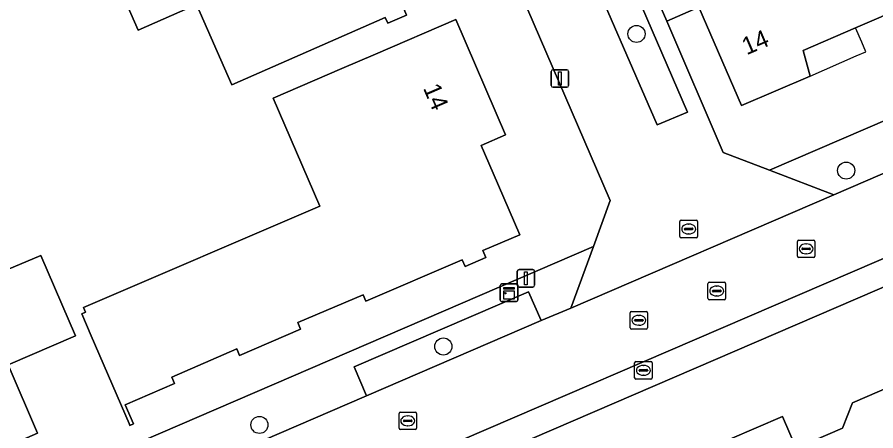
# Model space of a CAD drawing. Extents: x 157767 to 159172, y 387839 to 389425.
# Drawn here: x 158122.64 to 158171.64, y 388718.27 to 388741.89 of the extents above; entities that cross this region are included whole.
import ezdxf

# ---------------------------------------------------------------- set-up
doc = ezdxf.new("R2010")
doc.units = 0
for name, color, linetype in [('IMGEO_Boom', 7, 'Continuous'), ('IMGEO_Brandkraan', 7, 'Continuous'), ('IMGEO_Erf', 7, 'Continuous'), ('IMGEO_Kast', 7, 'Continuous'), ('IMGEO_Kolk', 7, 'Continuous'), ('IMGEO_Lichtmast', 7, 'Continuous'), ('IMGEO_Pand', 7, 'Continuous'), ('IMGEO_Pand_nummerreeks', 7, 'Continuous'), ('IMGEO_Pand_overbouw', 7, 'Continuous'), ('IMGEO_Parkeervlak_open', 7, 'Continuous'), ('IMGEO_Rijbaan_lokaal_open', 7, 'Continuous'), ('IMGEO_Rioolput', 7, 'Continuous'), ('IMGEO_Voetpad_open', 7, 'Continuous')]:
    doc.layers.add(name, color=color, linetype=linetype)

msp = doc.modelspace()

# ---------------------------------------------------------------- linework, layer by layer
at = {"layer": 'IMGEO_Boom'}
for centre in [(158157.983, 388740.927), (158169.948, 388733.125), (158146.961, 388723.083), (158136.464, 388718.604)]:
    msp.add_circle(centre, 0.489, dxfattribs=at)
at = {"layer": 'IMGEO_Brandkraan'}
for p, q in [((158157.876, 388721.292), (158157.876, 388722.144)), ((158157.951, 388722.218), (158158.803, 388722.218)), ((158158.364, 388721.998), (158158.389, 388721.998)), ((158158.877, 388722.144), (158158.877, 388721.292)), ((158158.135, 388721.712), (158158.135, 388721.724)), ((158158.573, 388721.675), (158158.175, 388721.675)), ((158158.178, 388721.761), (158158.576, 388721.761)), ((158158.387, 388721.438), (158158.362, 388721.438)), ((158158.619, 388721.724), (158158.619, 388721.712)), ((158158.803, 388721.218), (158157.951, 388721.218))]:
    msp.add_line(p, q, dxfattribs=at)
for points in [[(158157.876, 388721.292), (158157.876, 388722.144)], [(158157.951, 388722.218), (158158.803, 388722.218)], [(158158.877, 388722.144), (158158.877, 388721.292)], [(158158.803, 388721.218), (158157.951, 388721.218)]]:
    msp.add_lwpolyline(points, dxfattribs=at)
for centre, radius, start, end in [((158157.953, 388722.142), 0.0765, 91.552, 178.448), ((158157.953, 388722.142), 0.0765, 91.552, 178.448), ((158158.801, 388722.142), 0.0765, 1.552, 88.448), ((158158.801, 388722.142), 0.0765, 1.552, 88.448), ((158158.175, 388721.721), 0.0403, 85.8775, 175.7526), ((158158.172, 388721.711), 0.0366, 178.938, 274.7102), ((158158.576, 388721.718), 0.043, 264.8664, 352.4533), ((158158.58, 388721.723), 0.0386, 1.7309, 96.639), ((158157.953, 388721.294), 0.0765, 181.552, 268.448), ((158157.953, 388721.294), 0.0765, 181.552, 268.448), ((158158.801, 388721.294), 0.0765, 271.552, 358.448), ((158158.801, 388721.294), 0.0765, 271.552, 358.448)]:
    msp.add_arc(centre, radius, start, end, dxfattribs=at)
for centre, major_axis, ratio, start_param, end_param in [((158158.363, 388721.718), (-0.387, 0.002), 0.722429, 4.712389, 7.853982), ((158158.388, 388721.718), (-0.39, 0.002), 0.717154, 1.570796, 4.712389)]:
    msp.add_ellipse(centre, major_axis=major_axis, ratio=ratio, start_param=start_param, end_param=end_param, dxfattribs=at)
at = {"layer": 'IMGEO_Erf'}
for points in [[(158128.121, 388749.432), (158129.068, 388749.847), (158130.979, 388750.683), (158131.778, 388751.032), (158136.358, 388753.036), (158137.65, 388750.084), (158142.754, 388752.318), (158143.769, 388750), (158143.853, 388749.808), (158144.292, 388750), (158144.584, 388750.128), (158144.639, 388750), (158147.435, 388743.516), (158144.716, 388742.327), (158144.859, 388742.003), (158143.786, 388741.533), (158143.644, 388741.858), (158134.884, 388738.025), (158132.881, 388742.604), (158129.54, 388741.142), (158127.585, 388745.614), (158129.437, 388746.424)], [(158139.903, 388731.092), (158137.252, 388737.268), (158141.162, 388738.946), (158143.084, 388739.771), (158147.678, 388741.743), (158150.503, 388735.164), (158149.116, 388734.564), (158149.799, 388732.985), (158151.322, 388729.462), (158149.213, 388728.553), (158149.385, 388728.153), (158148.2, 388727.641), (158148.03, 388728.036), (158142.533, 388725.665), (158142.376, 388726.033), (158138.652, 388724.443), (158138.806, 388724.073), (158135.331, 388722.574), (158135.173, 388722.942), (158131.456, 388721.335), (158131.616, 388720.967), (158128.798, 388719.751), (158129.27, 388718.659), (158129.07, 388718.573), (158129.026, 388718.675), (158126.863, 388723.689), (158126.321, 388724.946), (158126.541, 388725.04), (158126.426, 388725.306)], [(158182.445, 388701.959), (158177.657, 388699.85), (158173.023, 388710.594), (158169.625, 388709.129), (158170.139, 388707.935), (158166.465, 388706.351), (158163.787, 388712.559), (158161.807, 388717.15), (158166.312, 388719.092), (158167.091, 388717.285), (158169.735, 388718.425), (158170.309, 388719.869), (158174.095, 388721.502), (158176.075, 388716.911)]]:
    msp.add_lwpolyline(points, close=True, dxfattribs=at)
for points in [[(158117.739, 388745.138), (158119.269, 388741.573), (158111.6, 388738.281), (158115.856, 388728.369), (158114.939, 388727.976), (158116.218, 388724.995), (158123.988, 388728.285), (158125.961, 388723.69), (158122.118, 388722.028), (158123.799, 388718.137), (158121.38, 388717.092), (158116.266, 388714.882), (158111.105, 388712.651), (158108.695, 388711.61), (158109.311, 388710.185), (158104.688, 388708.207), (158104.74, 388708.086), (158104.538, 388707.998), (158104.988, 388707.005), (158155.532, 388728.793), (158156.474, 388731.409), (158148.476, 388750)], [(158173.448, 388742.548), (158170.488, 388741.27), (158167.498, 388739.979), (158167.894, 388738.519), (158163.973, 388736.84), (158161.536, 388742.453), (158159.71, 388741.661), (158162.924, 388734.167), (158165.563, 388733.146), (158187.619, 388742.643)], [(158199.515, 388738.309), (158146.245, 388715.336), (158145.347, 388712.435), (158152.598, 388695.598), (158155.311, 388689.297), (158156.854, 388685.715), (158162.739, 388672.05), (158167.203, 388661.684), (158171.568, 388659.372), (158223.84, 388681.871)]]:
    msp.add_lwpolyline(points, dxfattribs=at)
at = {"layer": 'IMGEO_Kast'}
for p, q in [((158150.21, 388725.728), (158150.21, 388726.569)), ((158150.21, 388726.569), (158150.21, 388725.728)), ((158150.285, 388726.653), (158151.126, 388726.653)), ((158151.126, 388726.653), (158150.285, 388726.653)), ((158151.21, 388726.578), (158151.21, 388725.737)), ((158151.21, 388725.737), (158151.21, 388726.578)), ((158151.135, 388725.653), (158150.294, 388725.653)), ((158150.294, 388725.653), (158151.135, 388725.653))]:
    msp.add_line(p, q, dxfattribs=at)
for points in [[(158150.405, 388726.443), (158151.005, 388726.443), (158151.005, 388726.358), (158150.405, 388726.358), (158150.405, 388726.443)], [(158150.405, 388726.268), (158151.005, 388726.268), (158151.005, 388725.779), (158150.405, 388725.779), (158150.405, 388726.268)]]:
    msp.add_lwpolyline(points, dxfattribs=at)
msp.add_circle((158150.489, 388726.117), 0.0377, dxfattribs=at)
for centre, start, end in [((158150.288, 388726.575), 92.4484, 184.2845), ((158150.288, 388726.575), 92.4484, 184.2845), ((158151.132, 388726.575), 2.4484, 94.2845), ((158151.132, 388726.575), 2.4484, 94.2845), ((158150.288, 388725.731), 182.4484, 274.2845), ((158150.288, 388725.731), 182.4484, 274.2845), ((158151.132, 388725.731), 272.4484, 4.2845), ((158151.132, 388725.731), 272.4484, 4.2845)]:
    msp.add_arc(centre, 0.0779, start, end, dxfattribs=at)
at = {"layer": 'IMGEO_Kolk'}
for p, q in [((158160.459, 388729.362), (158160.459, 388730.214)), ((158160.534, 388730.288), (158161.386, 388730.288)), ((158161.46, 388730.214), (158161.46, 388729.362)), ((158160.718, 388729.782), (158160.718, 388729.794)), ((158161.156, 388729.745), (158160.758, 388729.745)), ((158160.761, 388729.831), (158161.159, 388729.831)), ((158160.947, 388730.068), (158160.972, 388730.068)), ((158161.202, 388729.794), (158161.202, 388729.782)), ((158161.386, 388729.288), (158160.534, 388729.288)), ((158160.97, 388729.508), (158160.945, 388729.508)), ((158167.162, 388728.232), (158167.162, 388729.084)), ((158167.237, 388729.158), (158168.089, 388729.158)), ((158167.464, 388728.701), (158167.862, 388728.701)), ((158167.65, 388728.938), (158167.675, 388728.938)), ((158168.163, 388729.084), (158168.163, 388728.232)), ((158167.421, 388728.652), (158167.421, 388728.664)), ((158167.859, 388728.615), (158167.461, 388728.615)), ((158167.673, 388728.378), (158167.648, 388728.378)), ((158167.905, 388728.664), (158167.905, 388728.652)), ((158168.089, 388728.158), (158167.237, 388728.158)), ((158157.615, 388724.152), (158157.615, 388725.004)), ((158157.69, 388725.078), (158158.542, 388725.078)), ((158158.103, 388724.858), (158158.128, 388724.858)), ((158158.616, 388725.004), (158158.616, 388724.152)), ((158157.874, 388724.572), (158157.874, 388724.584)), ((158158.312, 388724.535), (158157.914, 388724.535)), ((158157.917, 388724.621), (158158.315, 388724.621)), ((158158.126, 388724.298), (158158.101, 388724.298)), ((158158.358, 388724.584), (158158.358, 388724.572)), ((158158.542, 388724.078), (158157.69, 388724.078)), ((158144.429, 388718.411), (158144.429, 388719.263)), ((158144.504, 388719.337), (158145.356, 388719.337)), ((158144.917, 388719.117), (158144.942, 388719.117)), ((158145.43, 388719.263), (158145.43, 388718.411)), ((158144.688, 388718.831), (158144.688, 388718.843)), ((158145.126, 388718.794), (158144.728, 388718.794)), ((158144.731, 388718.88), (158145.129, 388718.88)), ((158144.94, 388718.557), (158144.915, 388718.557)), ((158145.172, 388718.843), (158145.172, 388718.831)), ((158145.356, 388718.337), (158144.504, 388718.337))]:
    msp.add_line(p, q, dxfattribs=at)
for points in [[(158160.459, 388729.362), (158160.459, 388730.214)], [(158160.534, 388730.288), (158161.386, 388730.288)], [(158161.46, 388730.214), (158161.46, 388729.362)], [(158161.386, 388729.288), (158160.534, 388729.288)], [(158167.162, 388728.232), (158167.162, 388729.084)], [(158167.237, 388729.158), (158168.089, 388729.158)], [(158168.163, 388729.084), (158168.163, 388728.232)], [(158168.089, 388728.158), (158167.237, 388728.158)], [(158157.615, 388724.152), (158157.615, 388725.004)], [(158157.69, 388725.078), (158158.542, 388725.078)], [(158158.616, 388725.004), (158158.616, 388724.152)], [(158158.542, 388724.078), (158157.69, 388724.078)], [(158144.429, 388718.411), (158144.429, 388719.263)], [(158144.504, 388719.337), (158145.356, 388719.337)], [(158145.43, 388719.263), (158145.43, 388718.411)], [(158145.356, 388718.337), (158144.504, 388718.337)]]:
    msp.add_lwpolyline(points, dxfattribs=at)
for centre, radius, start, end in [((158160.536, 388730.212), 0.0765, 91.552, 178.448), ((158160.536, 388730.212), 0.0765, 91.552, 178.448), ((158161.384, 388730.212), 0.0765, 1.552, 88.448), ((158161.384, 388730.212), 0.0765, 1.552, 88.448), ((158160.758, 388729.791), 0.0403, 85.8775, 175.7526), ((158160.755, 388729.781), 0.0366, 178.938, 274.7102), ((158161.159, 388729.788), 0.043, 264.8664, 352.4533), ((158161.163, 388729.793), 0.0386, 1.7309, 96.639), ((158160.536, 388729.364), 0.0765, 181.552, 268.448), ((158160.536, 388729.364), 0.0765, 181.552, 268.448), ((158161.384, 388729.364), 0.0765, 271.552, 358.448), ((158161.384, 388729.364), 0.0765, 271.552, 358.448), ((158167.239, 388729.082), 0.0765, 91.552, 178.448), ((158167.239, 388729.082), 0.0765, 91.552, 178.448), ((158167.461, 388728.661), 0.0403, 85.8775, 175.7526), ((158167.866, 388728.663), 0.0386, 1.7309, 96.639), ((158168.087, 388729.082), 0.0765, 1.552, 88.448), ((158168.087, 388729.082), 0.0765, 1.552, 88.448), ((158167.239, 388728.234), 0.0765, 181.552, 268.448), ((158167.239, 388728.234), 0.0765, 181.552, 268.448), ((158167.458, 388728.651), 0.0366, 178.938, 274.7102), ((158167.862, 388728.658), 0.043, 264.8664, 352.4533), ((158168.087, 388728.234), 0.0765, 271.552, 358.448), ((158168.087, 388728.234), 0.0765, 271.552, 358.448), ((158157.692, 388725.002), 0.0765, 91.552, 178.448), ((158157.692, 388725.002), 0.0765, 91.552, 178.448), ((158158.54, 388725.002), 0.0765, 1.552, 88.448), ((158158.54, 388725.002), 0.0765, 1.552, 88.448), ((158157.914, 388724.581), 0.0403, 85.8775, 175.7526), ((158157.911, 388724.571), 0.0366, 178.938, 274.7102), ((158158.315, 388724.578), 0.043, 264.8664, 352.4533), ((158158.319, 388724.583), 0.0386, 1.7309, 96.639), ((158157.692, 388724.154), 0.0765, 181.552, 268.448), ((158157.692, 388724.154), 0.0765, 181.552, 268.448), ((158158.54, 388724.154), 0.0765, 271.552, 358.448), ((158158.54, 388724.154), 0.0765, 271.552, 358.448), ((158144.506, 388719.261), 0.0765, 91.552, 178.448), ((158144.506, 388719.261), 0.0765, 91.552, 178.448), ((158145.354, 388719.261), 0.0765, 1.552, 88.448), ((158145.354, 388719.261), 0.0765, 1.552, 88.448), ((158144.506, 388718.413), 0.0765, 181.552, 268.448), ((158144.506, 388718.413), 0.0765, 181.552, 268.448), ((158144.728, 388718.84), 0.0403, 85.8775, 175.7526), ((158144.725, 388718.83), 0.0366, 178.938, 274.7102), ((158145.129, 388718.837), 0.043, 264.8664, 352.4533), ((158145.133, 388718.842), 0.0386, 1.7309, 96.639), ((158145.354, 388718.413), 0.0765, 271.552, 358.448), ((158145.354, 388718.413), 0.0765, 271.552, 358.448)]:
    msp.add_arc(centre, radius, start, end, dxfattribs=at)
for centre, major_axis, ratio, start_param, end_param in [((158160.946, 388729.788), (-0.387, 0.002), 0.722429, 4.712389, 7.853982), ((158160.971, 388729.788), (-0.39, 0.002), 0.717154, 1.570796, 4.712389), ((158167.649, 388728.658), (-0.387, 0.002), 0.722429, 4.712389, 7.853982), ((158167.674, 388728.658), (-0.39, 0.002), 0.717154, 1.570796, 4.712389), ((158158.102, 388724.578), (-0.387, 0.002), 0.722429, 4.712389, 7.853982), ((158158.127, 388724.578), (-0.39, 0.002), 0.717154, 1.570796, 4.712389), ((158144.916, 388718.837), (-0.387, 0.002), 0.722429, 4.712389, 7.853982), ((158144.941, 388718.837), (-0.39, 0.002), 0.717154, 1.570796, 4.712389)]:
    msp.add_ellipse(centre, major_axis=major_axis, ratio=ratio, start_param=start_param, end_param=end_param, dxfattribs=at)
at = {"layer": 'IMGEO_Lichtmast'}
for p, q in [((158153.118, 388737.984), (158153.118, 388738.784)), ((158153.118, 388738.784), (158153.118, 388737.984)), ((158153.218, 388738.884), (158154.008, 388738.884)), ((158154.008, 388738.884), (158153.218, 388738.884)), ((158154.108, 388738.784), (158154.108, 388737.984)), ((158154.108, 388737.984), (158154.108, 388738.784)), ((158154.008, 388737.884), (158153.218, 388737.884)), ((158153.218, 388737.884), (158154.008, 388737.884)), ((158151.177, 388726.574), (158151.177, 388727.374)), ((158151.177, 388727.374), (158151.177, 388726.574)), ((158151.277, 388727.474), (158152.067, 388727.474)), ((158152.067, 388727.474), (158151.277, 388727.474)), ((158152.167, 388727.374), (158152.167, 388726.574)), ((158152.167, 388726.574), (158152.167, 388727.374)), ((158152.067, 388726.474), (158151.277, 388726.474)), ((158151.277, 388726.474), (158152.067, 388726.474))]:
    msp.add_line(p, q, dxfattribs=at)
for points in [[(158153.538, 388738.759), (158153.688, 388738.759), (158153.688, 388738.009), (158153.538, 388738.009), (158153.538, 388738.759)], [(158151.597, 388727.349), (158151.747, 388727.349), (158151.747, 388726.599), (158151.597, 388726.599), (158151.597, 388727.349)]]:
    msp.add_lwpolyline(points, dxfattribs=at)
for centre, start, end in [((158153.218, 388738.784), 90, 180), ((158153.218, 388738.784), 90, 180), ((158154.008, 388738.784), 0, 90), ((158154.008, 388738.784), 360, 90), ((158153.218, 388737.984), 180, 270), ((158153.218, 388737.984), 180, 270), ((158154.008, 388737.984), 270, 0), ((158154.008, 388737.984), 270, 0), ((158151.277, 388727.374), 90, 180), ((158151.277, 388727.374), 90, 180), ((158152.067, 388727.374), 0, 90), ((158152.067, 388727.374), 360, 90), ((158151.277, 388726.574), 180, 270), ((158151.277, 388726.574), 180, 270), ((158152.067, 388726.574), 270, 0), ((158152.067, 388726.574), 270, 0)]:
    msp.add_arc(centre, 0.1, start, end, dxfattribs=at)
at = {"layer": 'IMGEO_Pand'}
for points in [[(158144.639, 388750), (158144.584, 388750.128), (158144.292, 388750), (158143.853, 388749.808), (158143.769, 388750), (158142.754, 388752.318), (158137.65, 388750.084), (158136.358, 388753.036), (158131.778, 388751.032), (158130.979, 388750.683), (158129.068, 388749.847), (158128.121, 388749.432), (158129.437, 388746.424), (158127.585, 388745.614), (158129.54, 388741.142), (158132.881, 388742.604), (158134.884, 388738.025), (158143.644, 388741.858), (158143.786, 388741.533), (158144.859, 388742.003), (158144.716, 388742.327), (158147.435, 388743.516)], [(158170.245, 388750), (158169.302, 388752.195), (158167.74, 388751.52), (158164.225, 388750), (158163.15, 388749.535), (158163.862, 388747.884), (158159.92, 388746.178), (158159.827, 388746.393), (158158, 388745.6), (158159.71, 388741.661), (158161.536, 388742.453), (158163.973, 388736.84), (158167.894, 388738.519), (158167.498, 388739.979), (158170.488, 388741.27), (158173.448, 388742.548)], [(158117.739, 388745.138), (158112.491, 388742.885), (158110.07, 388741.846), (158105.536, 388739.9), (158116.266, 388714.882), (158121.38, 388717.092), (158123.799, 388718.137), (158122.118, 388722.028), (158125.961, 388723.69), (158123.988, 388728.285), (158116.218, 388724.995), (158114.939, 388727.976), (158115.856, 388728.369), (158111.6, 388738.281), (158119.269, 388741.573)], [(158139.903, 388731.092), (158126.426, 388725.306), (158126.541, 388725.04), (158126.321, 388724.946), (158126.863, 388723.689), (158129.026, 388718.675), (158129.07, 388718.573), (158129.27, 388718.659), (158128.798, 388719.751), (158131.616, 388720.967), (158131.456, 388721.335), (158135.173, 388722.942), (158135.331, 388722.574), (158138.806, 388724.073), (158138.652, 388724.443), (158142.376, 388726.033), (158142.533, 388725.665), (158148.03, 388728.036), (158148.2, 388727.641), (158149.385, 388728.153), (158149.213, 388728.553), (158151.322, 388729.462), (158149.799, 388732.985), (158149.116, 388734.564), (158150.503, 388735.164), (158147.678, 388741.743), (158143.084, 388739.771), (158141.162, 388738.946), (158137.252, 388737.268)], [(158182.445, 388701.959), (158176.075, 388716.911), (158174.095, 388721.502), (158170.309, 388719.869), (158169.735, 388718.425), (158167.091, 388717.285), (158166.312, 388719.092), (158161.807, 388717.15), (158163.787, 388712.559), (158166.465, 388706.351), (158170.139, 388707.935), (158169.625, 388709.129), (158173.023, 388710.594), (158177.657, 388699.85)]]:
    msp.add_lwpolyline(points, close=True, dxfattribs=at)
at = {"layer": 'IMGEO_Pand_overbouw'}
msp.add_lwpolyline([(158170.488, 388741.27), (158167.498, 388739.979), (158167.894, 388738.519), (158170.526, 388739.672), (158171.076, 388739.91), (158170.843, 388740.451)], close=True, dxfattribs=at)
at = {"layer": 'IMGEO_Parkeervlak_open'}
for points in [[(158159.164, 388735.734), (158160.887, 388736.469), (158156.55, 388746.501), (158154.813, 388745.763)], [(158142.573, 388720.269), (158152.535, 388724.56), (158151.809, 388726.202), (158141.87, 388721.923)]]:
    msp.add_lwpolyline(points, close=True, dxfattribs=at)
at = {"layer": 'IMGEO_Rijbaan_lokaal_open'}
for points in [[(158211.85, 388745.262), (158209.916, 388749.563), (158209.72, 388750), (158208.536, 388752.656), (158202.38, 388750), (158189.483, 388744.405), (158190.927, 388741.104), (158169.237, 388731.746), (158154.227, 388725.276), (158152.535, 388724.56), (158142.573, 388720.269), (158123.746, 388712.134), (158113.525, 388707.726), (158106.201, 388704.567), (158103.519, 388703.4), (158102.109, 388706.697), (158087.045, 388700.215), (158089.145, 388695.349), (158090.25, 388692.79), (158124.222, 388707.486), (158134.627, 388711.957), (158145.024, 388716.464)], [(158156.55, 388746.501), (158160.887, 388736.469), (158159.164, 388735.734), (158154.813, 388745.763)]]:
    msp.add_lwpolyline(points, close=True, dxfattribs=at)
msp.add_lwpolyline([(158148.476, 388750), (158156.474, 388731.409), (158155.532, 388728.793), (158154.227, 388725.276), (158169.237, 388731.746), (158165.563, 388733.146), (158162.924, 388734.167), (158159.71, 388741.661), (158158, 388745.6)], dxfattribs=at)
at = {"layer": 'IMGEO_Rioolput'}
for p, q in [((158162.136, 388726.751), (158162.988, 388726.751)), ((158162.061, 388725.825), (158162.061, 388726.677)), ((158162.32, 388726.245), (158162.32, 388726.257)), ((158162.363, 388726.294), (158162.761, 388726.294)), ((158162.549, 388726.531), (158162.574, 388726.531)), ((158162.804, 388726.257), (158162.804, 388726.245)), ((158163.062, 388726.677), (158163.062, 388725.825)), ((158162.988, 388725.751), (158162.136, 388725.751)), ((158162.758, 388726.208), (158162.36, 388726.208)), ((158162.572, 388725.971), (158162.547, 388725.971))]:
    msp.add_line(p, q, dxfattribs=at)
for points in [[(158162.136, 388726.751), (158162.988, 388726.751)], [(158162.061, 388725.825), (158162.061, 388726.677)], [(158163.062, 388726.677), (158163.062, 388725.825)], [(158162.988, 388725.751), (158162.136, 388725.751)]]:
    msp.add_lwpolyline(points, dxfattribs=at)
for centre, radius, start, end in [((158162.138, 388726.675), 0.0765, 91.552, 178.448), ((158162.138, 388726.675), 0.0765, 91.552, 178.448), ((158162.986, 388726.675), 0.0765, 1.552, 88.448), ((158162.986, 388726.675), 0.0765, 1.552, 88.448), ((158162.36, 388726.254), 0.0403, 85.8775, 175.7526), ((158162.357, 388726.244), 0.0366, 178.938, 274.7102), ((158162.761, 388726.251), 0.043, 264.8664, 352.4533), ((158162.765, 388726.256), 0.0386, 1.7309, 96.639), ((158162.138, 388725.827), 0.0765, 181.552, 268.448), ((158162.138, 388725.827), 0.0765, 181.552, 268.448), ((158162.986, 388725.827), 0.0765, 271.552, 358.448), ((158162.986, 388725.827), 0.0765, 271.552, 358.448)]:
    msp.add_arc(centre, radius, start, end, dxfattribs=at)
for centre, major_axis, ratio, start_param, end_param in [((158162.548, 388726.251), (-0.387, 0.002), 0.722429, 4.712389, 7.853982), ((158162.573, 388726.251), (-0.39, 0.002), 0.717154, 1.570796, 4.712389)]:
    msp.add_ellipse(centre, major_axis=major_axis, ratio=ratio, start_param=start_param, end_param=end_param, dxfattribs=at)
at = {"layer": 'IMGEO_Voetpad_open'}
for points in [[(158211.85, 388745.262), (158145.024, 388716.464), (158144.408, 388714.545), (158146.245, 388715.336), (158199.515, 388738.309), (158202.295, 388739.488), (158204.129, 388740.284), (158209.8, 388742.746)], [(158187.619, 388742.643), (158165.563, 388733.146), (158169.237, 388731.746), (158190.927, 388741.104), (158189.483, 388744.405)]]:
    msp.add_lwpolyline(points, dxfattribs=at)
msp.add_lwpolyline([(158087.045, 388700.215), (158102.109, 388706.697), (158103.519, 388703.4), (158106.201, 388704.567), (158113.525, 388707.726), (158112.815, 388709.389), (158123.035, 388713.795), (158123.746, 388712.134), (158142.573, 388720.269), (158141.87, 388721.923), (158151.809, 388726.202), (158152.535, 388724.56), (158154.227, 388725.276), (158155.532, 388728.793), (158104.988, 388707.005), (158104.538, 388707.998), (158103.54, 388710.289), (158099.864, 388708.724), (158089.109, 388704.09), (158082.352, 388701.179), (158085.544, 388693.809), (158089.145, 388695.349)], close=True, dxfattribs=at)

# ---------------------------------------------------------------- texts
at = {"layer": 'IMGEO_Pand_nummerreeks'}
for rotation, p in [(23.1819, (158164.266, 388739.706)), (293.2385, (158145.787, 388737.835))]:
    msp.add_text('14', height=1, rotation=rotation, dxfattribs=at).set_placement(p)

doc.saveas('drawing.dxf')
